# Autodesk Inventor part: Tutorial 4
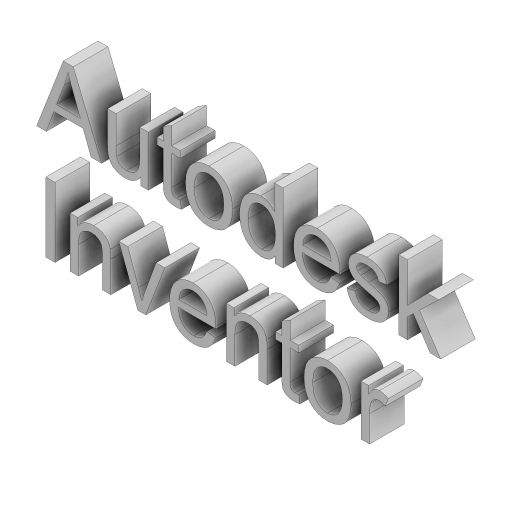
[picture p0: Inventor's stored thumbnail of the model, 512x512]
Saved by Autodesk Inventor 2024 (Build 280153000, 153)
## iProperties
Created: 2021-04
Part Number: Tutorial 4
Material: Generic
Document SubType Name: Modeling
Designer: ASUS Laptop
Density: 1 g/cm^3
Appearance: Default
Author: ASUS Laptop
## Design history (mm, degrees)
sketch "Sketch1"
  geometry: L1 (4.899, 17.404)-(34.549, 17.404); L2 (34.549, 17.404)-(34.549, 2.449); L3 (34.549, 2.449)-(4.899, 2.449); L4 (4.899, 2.449)-(4.899, 17.404); 1 further point
  constraints: 2 other
extrude "Extrusion1" new body sketch "Sketch1" distance "d0" = 2.5; taper "d1" = 0 deg
body "Solid1"
